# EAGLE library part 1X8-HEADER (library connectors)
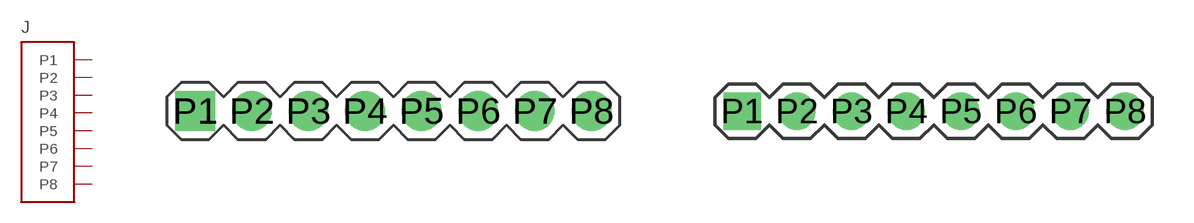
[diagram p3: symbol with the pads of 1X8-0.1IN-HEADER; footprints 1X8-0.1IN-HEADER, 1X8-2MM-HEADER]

Designator prefix J

## 1X8-HEADER0.1IN  [1X8-0.1IN-HEADER]
P1  P1  pas
P2  P2  pas
P3  P3  pas
P4  P4  pas
P5  P5  pas
P6  P6  pas
P7  P7  pas
P8  P8  pas

## 1X8-HEADER2MM  [1X8-2MM-HEADER]
Pads as for 1X8-0.1IN-HEADER

## Footprint 1X8-0.1IN-HEADER (pad centres in mm)
drill 1.05 pad 1.778 square: P1 -8.89,0
drill 1.05 pad 1.778 round: P2 -6.35,0; P3 -3.81,0; P4 -1.27,0; P5 1.27,0; P6 3.81,0; P7 6.35,0; P8 8.89,0

## Footprint 1X8-2MM-HEADER (pad centres in mm)
drill 0.85 square: P1 -7,0
drill 0.85 round: P2 -5,0; P3 -3,0; P4 -1,0; P5 1,0; P6 3,0; P7 5,0; P8 7,0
